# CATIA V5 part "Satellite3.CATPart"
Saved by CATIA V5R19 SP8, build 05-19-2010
Part number: Satellite3
Bounding box of the stored display mesh (mm): x 0 to 14, y -20 to 20, z 15 to 55
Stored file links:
  G:\EU_thinkMotion\CFAO_2010\SIL_groupe2\SIL_groupe2\msauret\Brevet_Sauret_parametre\Satellite3.CATPart
  F:\Brevet_Sauret paramétré\Product3.CATProduct
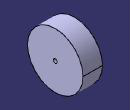
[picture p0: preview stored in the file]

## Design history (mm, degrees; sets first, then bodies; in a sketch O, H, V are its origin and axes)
Set1
  Plane1: linked copy from another document
  Point1: linked copy from another document
  Plane2: linked copy from another document
Body1 (main body)
  Sketch1 on Plane1, origin (0, 0, 0), H (0, 1, 0), V (0, 0, 1)
    circle A1 centre (0, 35) radius 20
    point P1 (0, 35)
    reference projected point E1 (0, 35) from Point1
    distance P1 E1 = 0
    coincidence: P1 V
  Pad1: profile Sketch1, direction (1, 0, 0), up to Plane2
  Sketch2 on Plane1, origin (0, 0, 0), H (0, 1, 0), V (0, 0, 1)
    circle A1 centre (0, 34.7742) radius 1.5
    point P1 (0, 34.7742)
    coincidence: P1 V
  Pocket1: profile Sketch2, direction (-1, 0, 0), up to Plane2
  Plane3: type Offset, RefPlane yz-plane, Offset 9
  Sketch3 on Plane3, origin (9, 0, 0), H (0, 1, 0), V (0, 0, 1)
    circle A1 centre (0, 35) radius 20
    reference projected circle E1 centre (0, 35) radius 20 from edge [face of Pad1 from Sketch1.A1 | end face of Pad1]
    coincidence: A1 E1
